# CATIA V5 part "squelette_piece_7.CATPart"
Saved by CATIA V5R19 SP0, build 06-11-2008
Part number: squelette_piece_7
Publications: "Droite.1", "Point.1"
Bounding box of the stored display mesh (mm): x 0 to 0, y 0 to 63.5, z -500 to 94
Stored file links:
  D:\Documents\IFMA\S3\CFAO\projet_CFAO\squelette_piece_7.CATPart
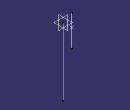
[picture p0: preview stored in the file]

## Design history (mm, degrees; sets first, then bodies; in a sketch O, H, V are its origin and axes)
Set1
  Line1: type PtDir, Direction Line2, Start -94, End 134, RefPoint Point1
  Point1: stored without definition
  Line2: stored without definition
Body1 (main body)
